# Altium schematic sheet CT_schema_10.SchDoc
size 147 x 119 mm
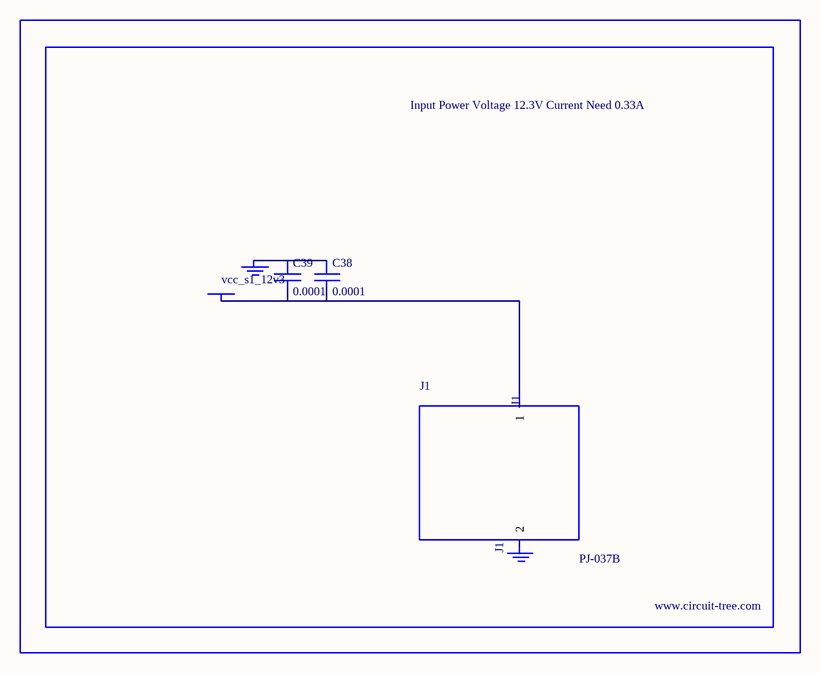
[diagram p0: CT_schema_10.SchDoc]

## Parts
BORDER9  (no value)
C38  0.0001  [EXV-9H]
C39  0.0001  [EXV-9H]
GND_INSTANCE_9_0  (no value)
GND_INSTANCE_9_1  (no value)
J1  PJ-037B  [PJ-037B_PACKAGE]
POWER_INSTANCE_9_0  vcc_s1_12v3

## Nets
NetC38_1: C38.1 C39.1 GND_INSTANCE_9_0.0(GND)
NetC38_2: C38.2 C39.2 J1.1 POWER_INSTANCE_9_0.0(PWR)

Not connected (* = marked no-connect by the designer): GND_INSTANCE_9_1 0(GND); J1 2

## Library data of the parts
BORDER9 = BORDER_PAGE9
C38 C39 = EDK107M035A9HAA
GND_INSTANCE_9_0 GND_INSTANCE_9_1 = GND
POWER_INSTANCE_9_0 = PWR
